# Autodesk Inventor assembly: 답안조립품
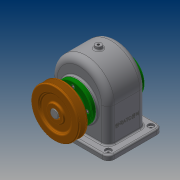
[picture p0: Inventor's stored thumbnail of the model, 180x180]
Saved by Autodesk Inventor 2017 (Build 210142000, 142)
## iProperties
Part Number: 답안조립품
Material: 일반
Document SubType Name: Assembly
Designer: 20
Author: 20
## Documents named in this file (13)
- C:\Users\20\Desktop\480310V1005\답안조립품.iam
- C:\Users\20\Desktop\480310V1005\본체.ipt
- C:\Users\20\Desktop\480310V1005\뒤커버.ipt
- C:\Users\20\Desktop\480310V1005\앞커버.ipt
- C:\Users\20\Desktop\480310V1005\오일 실 28 40 8.ipt
- C:\Users\20\Desktop\480310V1005\베어링 6203.ipt
- C:\Users\20\Desktop\480310V1005\축.ipt
- C:\Users\20\Desktop\480310V1005\스퍼기어.ipt
- C:\Users\20\Desktop\480310V1005\키 6x6x22.ipt
- C:\Users\20\Desktop\480310V1005\V-벨트풀리.ipt
- C:\Users\20\Desktop\480310V1005\키 5x5x18.ipt
- C:\Users\20\Desktop\480310V1005\멈춤나사 M4.ipt
- C:\Users\20\Desktop\480310V1005\볼트 M4.ipt
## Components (1 placed, 1 different names)
1. V-벨트풀리:1 — 플러쉬:2
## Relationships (1: Flush 1)
- 플러쉬:2 [Flush]: V-벨트풀리:1
